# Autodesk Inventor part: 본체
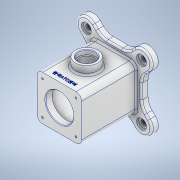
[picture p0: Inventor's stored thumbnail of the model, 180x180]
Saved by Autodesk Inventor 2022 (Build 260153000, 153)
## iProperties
Created: 2022-05
Part Number: 본체
Material: 알루미늄 6061
Document SubType Name: Modeling
Designer: Admin
Mass: 1072.55 g
Surface Area: 894.235 cm^2
Volume: 397.242 cm^3
Density: 2.7 g/cm^3
Appearance: 알루미늄 - 평지
Author: Admin
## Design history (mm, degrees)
sketch "스케치1"
  geometry: L1 (0, -56)-(0, 56) reference; L2 (-56, 0)-(56, 0) reference; L3 (-40, 40)-(40, 40); L4 (40, 40)-(40, -40); L5 (40, -40)-(-40, -40); L6 (-40, -40)-(-40, 40); L7 (-40, 40)-(40, -40); L8 (40, 40)-(-40, -40); 1 further point
  constraints: 12 end point, 2 midpoint, 2 parallel, 1 horizontal, 1 perpendicular
  dimensions: "d0" = 80 distance of L3.end L4.end; "d1" = 80 distance of L3.start L3.end
extrude "돌출1" new body sketch "스케치1" stored distance "d2" = 110; taper "d3" = 0 deg
sketch "스케치2"
  geometry: L1 (49, 49)-(-49, 49); L2 (-49, 49)-(-49, -49); L3 (-49, -49)-(49, -49); L4 (49, -49)-(49, 49); L5 (49, 49)-(-49, -49); L6 (-49, 49)-(49, -49); L7 (49.497, 49.497)-(-49.497, -49.497); L8 (36.77, 62.225)-(-62.225, -36.77); L9 (-36.77, -62.225)-(62.225, 36.77); L10 (-49.497, 49.497)-(49.497, -49.497); L11 (-62.225, 36.77)-(36.77, -62.225); L12 (62.225, -36.77)-(-36.77, 62.225); A1 r 18 centre (49.497, 49.497) between (62.225, 36.77) and (36.77, 62.225); A2 r 18 centre (-49.497, -49.497) between (-62.225, -36.77) and (-36.77, -62.225); A3 r 18 centre (-49.497, 49.497) between (-36.77, 62.225) and (-62.225, 36.77); A4 r 18 centre (49.497, -49.497) between (36.77, -62.225) and (62.225, -36.77); A5 r 70 centre (0, 0) between (49.497, 49.497) and (-49.497, 49.497); 13 further points
  constraints: 28 end point, 10 point on circle, 8 tangent, 6 midpoint, 5 centre point, 4 parallel, 3 coincident, 2 collinear, 1 horizontal, 1 perpendicular
  dimensions: "d4" = 98 distance of L2.end L3.end; "d5" = 98 distance of L3.end L1.start; "d6" = 36 distance between parallel lines of L8 L9; "d7" = 140 diameter of A5; "d9" = 36 distance between parallel lines of L11 L12
extrude "돌출2" join sketch "스케치2" distance "d10" = 12; taper "d11" = 0 deg
sketch "스케치3"
  geometry: L1 (-27.497, 98)-(3.23, 98) reference; C1 r 20 at (40, 49); 2 further points
  constraints: 1 centre point, 1 vertical alignment
  dimensions: "d12" = 49 distance from line of C1.centre L1; "d13" = 40 diameter of C1
extrude "돌출3" join sketch "스케치3" stored distance "d14" = 55; taper "d15" = 0 deg
sketch "스케치4"
  geometry: L1 (-94.496, 0)-(94.496, 0) reference; L2 (0, -77)-(0, 77) reference; L3 (40, 55)-(-40, 55) reference; L4 (25, 55)-(25, 43); L5 (25, 43)-(35, 43); L6 (35, 43)-(35, -43); L7 (35, -43)-(25, -43); L8 (25, -43)-(25, -55); L9 (-23.544, -55)-(23.544, -55) reference; L10 (25, 55)-(0, 55); L11 (0, 55)-(0, -55); L12 (0, -55)-(25, -55); L13 (23.544, -55)-(23.544, -43) reference; 2 further points
  constraints: 16 end point, 4 perpendicular, 4 point on line, 2 midpoint, 1 parallel
  dimensions: "d16" = 70 diameter of L6 L2; "d17" = 12 distance of L4.start L4.end; "d18" = 12 distance of L7.end L8.end; "d19" = 50 diameter of L4 L2
revolve "회전1" sketch "스케치4" stored, may be unused: angle "d20" = 90 deg
sketch "스케치5"
  geometry: C1 r 20 at (0, 0) reference; 2 further points
  constraints: 1 coincident
hole "구멍1" sketch "스케치5" at (0, 0) diameter "d21" = 25; stored, may be unused: countersink angle "d25" = 90 deg, drill point angle "d27" = 0 deg; dims "d22" = 6, "d23" = 30, "d24" = 8, "d26" = 8
sketch "스케치6"
  geometry: A1 r 18 centre (-49.497, 49.497) between (-36.77, 62.225) and (-62.225, 36.77) reference; A2 r 18 centre (49.497, 49.497) between (62.225, 36.77) and (36.77, 62.225) reference; A3 r 18 centre (49.497, -49.497) between (36.77, -62.225) and (62.225, -36.77) reference; A4 r 18 centre (-49.497, -49.497) between (-62.225, -36.77) and (-36.77, -62.225) reference; 5 further points
  constraints: 4 coincident
hole "구멍2" sketch "스케치6" at (-49.497, 49.497), (49.497, 49.497), (49.497, -49.497), (-49.497, -49.497) diameter "d28" = 10; stored, may be unused: countersink angle "d32" = 90 deg, drill point angle "d34" = 0 deg; dims "d29" = 6, "d30" = 18, "d31" = 4, "d33" = 8
fillet "모깎기1" dims "d35" = 10
sketch "스케치7"
  geometry: L1 (-30, -40)-(30, -40) reference; L2 (40, -30)-(40, 30) reference; L3 (30, 40)-(-30, 40) reference; L4 (-40, 30)-(-40, -30) reference; C1 r 25 at (0, 0) reference; A1 r 10 centre (-30, -30) between (-40, -30) and (-30, -40) reference; A2 r 10 centre (30, -30) between (30, -40) and (40, -30) reference; A3 r 10 centre (30, 30) between (40, 30) and (30, 40) reference; A4 r 10 centre (-30, 30) between (-30, 40) and (-40, 30) reference; 5 further points
  constraints: 4 coincident
hole "구멍3" sketch "스케치7" at (-30, 30), (30, 30), (30, -30), (-30, -30) diameter "d36" = 3.242; stored, may be unused: countersink angle "d40" = 90 deg, drill point angle "d42" = 118 deg; dims "d37" = 8, "d38" = 18, "d39" = 4, "d41" = 10
fillet "모깎기2" dims "d43" = 25
fillet "모깎기3" dims "d44" = 3
chamfer "모따기1" distance "d45" = 1; stored, may be unused: second distance "d46" = 2, angle "d47" = 45 deg
sketch "스케치8"
  geometry: L1 (60, 0)-(0, 0) reference; 2 further points
  constraints: 1 vertical alignment, 1 other
  dimensions: "d48" = 10 distance from line of L1 point (30, 10)
feature "엠보싱1" sketch "스케치8" dims "d0" = 80, "d1" = 80, "d4" = 98, "d5" = 98, "d6" = 36, "d7" = 140, "d9" = 36, "d49" = 0.5, "d50" = 0
sketch "스케치9"
  geometry: L1 (0, -94.496)-(0, 94.496) reference; L2 (94.496, 0)-(-94.496, 0) reference; 5 further points
  constraints: 4 symmetric about line
  dimensions: "d51" = 60 distance of point (-30, -35.735) point (30, -35.735)
hole "구멍4" sketch "스케치9" at (30, 35.735), (30, -35.735), (-30, -35.735), (-30, 35.735) diameter "d52" = 3.242; stored, may be unused: countersink angle "d56" = 90 deg, drill point angle "d58" = 118 deg; dims "d53" = 8, "d54" = 4, "d55" = 2, "d57" = 10
node "솔리드1"
node "투영된 루프1"
feature "A9D066F2-1C7D-4E18-AEED-F7BC21143FA4" dims "d28" = 10, "d29" = 6, "d30" = 18, "d31" = 4, "d32" = 90 deg, "d33" = 8, "d34" = 0
